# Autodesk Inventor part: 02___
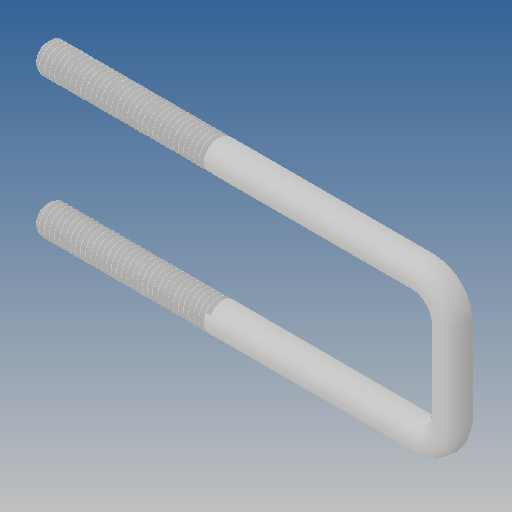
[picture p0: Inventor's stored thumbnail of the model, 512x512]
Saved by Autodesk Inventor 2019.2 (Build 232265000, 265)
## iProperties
Created: 2010-06
Part Number: 02___
Material: Ogólny
Document SubType Name: Modeling
Designer: CADENGINEERING4
Density: 1 g/cm^3
Appearance: Domyślna
Author: CADENGINEERING4
Revision Number: ANY
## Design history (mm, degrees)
feature "NONE"
node "Bryła1"
